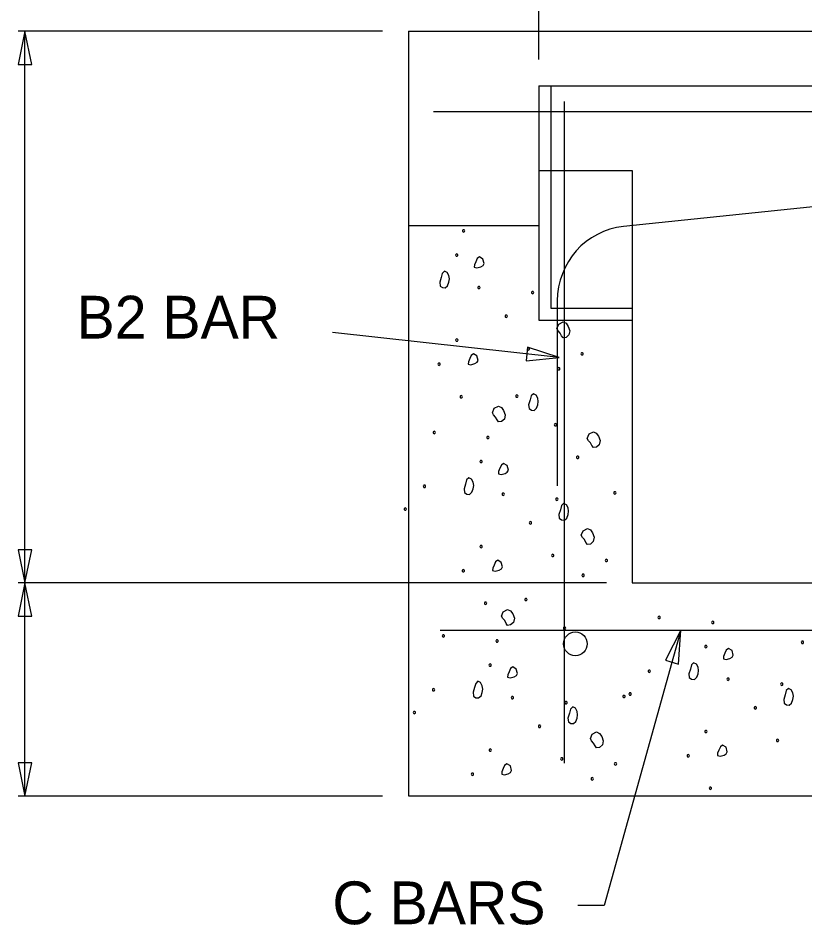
# Model space of a CAD drawing. Extents: x -439.2 to -407.9, y -458.1 to -436.2.
# Drawn here: x -415.176 to -412.38, y -445.047 to -441.825 of the extents above; entities that cross this region are included whole.
import ezdxf

# ---------------------------------------------------------------- set-up
doc = ezdxf.new("R2010")
doc.units = 0
doc.layers.add('Level 4', color=7, linetype='Continuous')

msp = doc.modelspace()

# ---------------------------------------------------------------- linework, layer by layer
at = {"layer": 'Level 4'}
for p, q in [((-413.3253, -441.9721), (-413.3253, -441.3025)), ((-413.881, -441.8718), (-415.1764, -441.8718)), ((-415.1523, -443.8317), (-415.1523, -441.8718)), ((-413.7894, -441.872), (-413.7894, -444.5887)), ((-413.7894, -441.872), (-409.204, -441.872)), ((-413.3253, -442.0658), (-409.7091, -442.0658)), ((-413.3253, -442.0658), (-413.3253, -442.8986)), ((-413.2833, -442.0658), (-413.2833, -442.856)), ((-413.236, -442.1212), (-413.236, -444.4726)), ((-413.7001, -442.1574), (-409.2933, -442.1574)), ((-413.3253, -442.3661), (-412.9935, -442.3661)), ((-411.0363, -442.3587), (-413.0244, -442.5652)), ((-412.9935, -442.3661), (-412.9935, -443.8315)), ((-413.7894, -442.5621), (-413.3253, -442.5621)), ((-413.2602, -442.8301), (-413.2602, -443.4865)), ((-413.2833, -442.856), (-412.9935, -442.856)), ((-413.3253, -442.8986), (-412.9935, -442.8986)), ((-413.2532, -443.0313), (-414.0594, -442.9419)), ((-413.0849, -443.8317), (-415.1764, -443.8317)), ((-415.1523, -444.5888), (-415.1523, -443.8317)), ((-412.9935, -443.8315), (-411.8957, -443.8315)), ((-413.676, -443.9998), (-409.2933, -443.9998)), ((-412.8209, -444), (-413.0931, -444.9774)), ((-413.881, -444.5888), (-415.1764, -444.5888)), ((-413.7894, -444.5887), (-409.204, -444.5887)), ((-413.0931, -444.9774), (-413.1873, -444.9774))]:
    msp.add_line(p, q, dxfattribs=at)
for points in [[(-415.1281, -441.9897), (-415.1523, -441.8718), (-415.1764, -441.9897)], [(-413.5372, -442.6735), (-413.545, -442.6795), (-413.5502, -442.6906), (-413.555, -442.702), (-413.5554, -442.7104), (-413.5459, -442.7127), (-413.532, -442.709), (-413.5242, -442.7042), (-413.5203, -442.6972), (-413.5246, -442.681), (-413.5372, -442.6735)], [(-413.661, -442.7243), (-413.669, -442.7319), (-413.6727, -442.7467), (-413.678, -442.7637), (-413.6766, -442.777), (-413.6684, -442.7826), (-413.6584, -442.7836), (-413.65, -442.7761), (-413.6455, -442.7638), (-413.6436, -442.7519), (-413.6455, -442.7401), (-413.6515, -442.7291), (-413.661, -442.7243)], [(-413.2615, -442.9283), (-413.2549, -442.9123), (-413.2394, -442.9046), (-413.2291, -442.9095), (-413.2212, -442.9204), (-413.2155, -442.9358), (-413.2186, -442.9506), (-413.2287, -442.9596), (-413.2394, -442.9612), (-413.2448, -442.954), (-413.2498, -442.9441), (-413.2568, -442.9364), (-413.2615, -442.9283)], [(-413.5583, -443.0173), (-413.5661, -443.0233), (-413.5713, -443.0344), (-413.576, -443.0458), (-413.5764, -443.0541), (-413.567, -443.0565), (-413.5531, -443.0528), (-413.5453, -443.048), (-413.5414, -443.041), (-413.5456, -443.0248), (-413.5583, -443.0173)], [(-413.3713, -443.0428), (-413.2532, -443.0313), (-413.366, -442.9942)], [(-413.3451, -443.1594), (-413.353, -443.1669), (-413.3567, -443.1818), (-413.362, -443.1988), (-413.3606, -443.212), (-413.3524, -443.2177), (-413.3425, -443.2186), (-413.334, -443.2111), (-413.3295, -443.1989), (-413.3277, -443.187), (-413.3295, -443.1752), (-413.3355, -443.1642), (-413.3451, -443.1594)], [(-413.491, -443.227), (-413.4845, -443.2111), (-413.469, -443.2033), (-413.4587, -443.2083), (-413.4508, -443.2191), (-413.4451, -443.2346), (-413.4482, -443.2494), (-413.4583, -443.2584), (-413.469, -443.2599), (-413.4744, -443.2528), (-413.4794, -443.2428), (-413.4864, -443.2351), (-413.491, -443.227)], [(-413.154, -443.3183), (-413.1474, -443.3024), (-413.1319, -443.2946), (-413.1216, -443.2995), (-413.1138, -443.3104), (-413.1081, -443.3259), (-413.1112, -443.3407), (-413.1212, -443.3497), (-413.1319, -443.3512), (-413.1374, -443.3441), (-413.1423, -443.3341), (-413.1493, -443.3264), (-413.154, -443.3183)], [(-413.4508, -443.4073), (-413.4586, -443.4133), (-413.4638, -443.4244), (-413.4686, -443.4358), (-413.469, -443.4442), (-413.4595, -443.4466), (-413.4456, -443.4429), (-413.4378, -443.438), (-413.4339, -443.431), (-413.4382, -443.4148), (-413.4508, -443.4073)], [(-413.5746, -443.4581), (-413.5826, -443.4657), (-413.5863, -443.4805), (-413.5916, -443.4975), (-413.5902, -443.5108), (-413.582, -443.5165), (-413.572, -443.5174), (-413.5636, -443.5099), (-413.5591, -443.4976), (-413.5572, -443.4857), (-413.5591, -443.4739), (-413.5651, -443.463), (-413.5746, -443.4581)], [(-413.2376, -443.5494), (-413.2455, -443.557), (-413.2493, -443.5718), (-413.2546, -443.5888), (-413.2532, -443.6021), (-413.245, -443.6078), (-413.235, -443.6087), (-413.2266, -443.6012), (-413.222, -443.5889), (-413.2202, -443.577), (-413.222, -443.5652), (-413.228, -443.5543), (-413.2376, -443.5494)], [(-413.1751, -443.6621), (-413.1685, -443.6461), (-413.153, -443.6384), (-413.1427, -443.6433), (-413.1348, -443.6542), (-413.1291, -443.6697), (-413.1322, -443.6845), (-413.1423, -443.6935), (-413.153, -443.695), (-413.1585, -443.6879), (-413.1634, -443.6779), (-413.1704, -443.6702), (-413.1751, -443.6621)], [(-415.1764, -443.7139), (-415.1523, -443.8317), (-415.1281, -443.7139)], [(-413.4719, -443.7511), (-413.4797, -443.7571), (-413.4849, -443.7682), (-413.4896, -443.7796), (-413.4901, -443.788), (-413.4806, -443.7904), (-413.4667, -443.7867), (-413.4589, -443.7818), (-413.455, -443.7748), (-413.4593, -443.7586), (-413.4719, -443.7511)], [(-415.1281, -443.9496), (-415.1523, -443.8317), (-415.1764, -443.9496)], [(-413.4586, -443.9499), (-413.4521, -443.9339), (-413.4366, -443.9262), (-413.4263, -443.9311), (-413.4184, -443.942), (-413.4127, -443.9575), (-413.4158, -443.9723), (-413.4259, -443.9812), (-413.4366, -443.9828), (-413.442, -443.9757), (-413.447, -443.9657), (-413.454, -443.958), (-413.4586, -443.9499)], [(-412.8292, -444.12), (-412.8209, -444), (-412.8757, -444.1067)], [(-412.6517, -444.0645), (-412.6595, -444.0705), (-412.6647, -444.0816), (-412.6695, -444.093), (-412.6699, -444.1014), (-412.6604, -444.1037), (-412.6465, -444.1), (-412.6387, -444.0952), (-412.6348, -444.0882), (-412.6391, -444.072), (-412.6517, -444.0645)], [(-412.7755, -444.1153), (-412.7835, -444.1228), (-412.7872, -444.1377), (-412.7925, -444.1547), (-412.7911, -444.168), (-412.7829, -444.1736), (-412.7729, -444.1746), (-412.7645, -444.1671), (-412.76, -444.1548), (-412.7581, -444.1429), (-412.76, -444.1311), (-412.766, -444.1201), (-412.7755, -444.1153)], [(-413.4184, -444.1302), (-413.4262, -444.1362), (-413.4314, -444.1473), (-413.4362, -444.1587), (-413.4366, -444.1671), (-413.4271, -444.1694), (-413.4132, -444.1658), (-413.4055, -444.1609), (-413.4015, -444.1539), (-413.4058, -444.1377), (-413.4184, -444.1302)], [(-413.5422, -444.181), (-413.5502, -444.1886), (-413.5539, -444.2034), (-413.5592, -444.2204), (-413.5578, -444.2337), (-413.5496, -444.2394), (-413.5397, -444.2403), (-413.5312, -444.2328), (-413.5267, -444.2205), (-413.5248, -444.2086), (-413.5267, -444.1968), (-413.5327, -444.1858), (-413.5422, -444.181)], [(-412.4385, -444.2066), (-412.4464, -444.2141), (-412.4502, -444.229), (-412.4555, -444.246), (-412.4541, -444.2593), (-412.4459, -444.2649), (-412.4359, -444.2658), (-412.4275, -444.2584), (-412.4229, -444.2461), (-412.4211, -444.2342), (-412.4229, -444.2224), (-412.4289, -444.2114), (-412.4385, -444.2066)], [(-413.2052, -444.2723), (-413.2131, -444.2799), (-413.2169, -444.2947), (-413.2222, -444.3117), (-413.2208, -444.325), (-413.2126, -444.3306), (-413.2026, -444.3316), (-413.1942, -444.3241), (-413.1896, -444.3118), (-413.1878, -444.2999), (-413.1896, -444.2881), (-413.1956, -444.2771), (-413.2052, -444.2723)], [(-413.1427, -444.385), (-413.1361, -444.369), (-413.1206, -444.3613), (-413.1103, -444.3662), (-413.1024, -444.3771), (-413.0967, -444.3926), (-413.0998, -444.4074), (-413.1099, -444.4163), (-413.1206, -444.4179), (-413.1261, -444.4107), (-413.131, -444.4008), (-413.138, -444.3931), (-413.1427, -444.385)], [(-412.6728, -444.4083), (-412.6806, -444.4143), (-412.6858, -444.4254), (-412.6905, -444.4368), (-412.6909, -444.4451), (-412.6815, -444.4475), (-412.6676, -444.4438), (-412.6598, -444.439), (-412.6559, -444.432), (-412.6601, -444.4158), (-412.6728, -444.4083)], [(-415.1764, -444.471), (-415.1523, -444.5888), (-415.1281, -444.471)], [(-413.4395, -444.474), (-413.4473, -444.48), (-413.4525, -444.4911), (-413.4572, -444.5025), (-413.4577, -444.5109), (-413.4482, -444.5132), (-413.4343, -444.5095), (-413.4265, -444.5047), (-413.4226, -444.4977), (-413.4269, -444.4815), (-413.4395, -444.474)]]:
    msp.add_lwpolyline(points, close=True, dxfattribs=at)
for centre, major_axis, start_param, end_param in [((-412.9977, -442.8301), (0, 0.2662), 0.102079, 1.570796), ((-413.593, -442.5812), (0, 0.00422), 4.712389, 7.853982), ((-413.593, -442.5812), (0, 0.00422), 1.570796, 4.712389), ((-413.6176, -442.667), (0, 0.00422), 4.712389, 7.853982), ((-413.6176, -442.667), (0, 0.00422), 1.570796, 4.712389), ((-413.5387, -442.7826), (0, 0.00422), 4.712389, 7.853982), ((-413.5387, -442.7826), (0, 0.00422), 1.570796, 4.712389), ((-413.3479, -442.8004), (0, 0.00422), 4.712389, 7.853982), ((-413.3479, -442.8004), (0, 0.00422), 1.570796, 4.712389), ((-413.4418, -442.8845), (0, 0.00422), 4.712389, 7.853982), ((-413.4418, -442.8845), (0, 0.00422), 1.570796, 4.712389), ((-413.6172, -442.9689), (0, 0.00422), 4.712389, 7.853982), ((-413.6172, -442.9689), (0, 0.00422), 1.570796, 4.712389), ((-413.3629, -443.0002), (0, 0.00422), 4.712389, 7.853982), ((-413.3629, -443.0002), (0, 0.00422), 1.570796, 4.712389), ((-413.1721, -443.018), (0, 0.00422), 4.712389, 7.853982), ((-413.1721, -443.018), (0, 0.00422), 1.570796, 4.712389), ((-413.6805, -443.0546), (0, 0.00422), 4.712389, 7.853982), ((-413.6805, -443.0546), (0, 0.00422), 1.570796, 4.712389), ((-413.2548, -443.071), (0, 0.00422), 4.712389, 7.853982), ((-413.2548, -443.071), (0, 0.00422), 1.570796, 4.712389), ((-413.6016, -443.1703), (0, 0.00422), 4.712389, 7.853982), ((-413.6016, -443.1703), (0, 0.00422), 1.570796, 4.712389), ((-413.4039, -443.1681), (0, 0.00422), 4.712389, 7.853982), ((-413.4039, -443.1681), (0, 0.00422), 1.570796, 4.712389), ((-413.2668, -443.27), (0, 0.00422), 4.712389, 7.853982), ((-413.2668, -443.27), (0, 0.00422), 1.570796, 4.712389), ((-413.6974, -443.2973), (0, 0.00422), 4.712389, 7.853982), ((-413.6974, -443.2973), (0, 0.00422), 1.570796, 4.712389), ((-413.5066, -443.3151), (0, 0.00422), 4.712389, 7.853982), ((-413.5066, -443.3151), (0, 0.00422), 1.570796, 4.712389), ((-413.5312, -443.4008), (0, 0.00422), 4.712389, 7.853982), ((-413.5312, -443.4008), (0, 0.00422), 1.570796, 4.712389), ((-413.1878, -443.3856), (0, 0.00422), 4.712389, 7.853982), ((-413.1878, -443.3856), (0, 0.00422), 1.570796, 4.712389), ((-413.7324, -443.4885), (0, 0.00422), 4.712389, 7.853982), ((-413.7324, -443.4885), (0, 0.00422), 1.570796, 4.712389), ((-413.4523, -443.5165), (0, 0.00422), 4.712389, 7.853982), ((-413.4523, -443.5165), (0, 0.00422), 1.570796, 4.712389), ((-413.2615, -443.5343), (0, 0.00422), 4.712389, 7.853982), ((-413.2615, -443.5343), (0, 0.00422), 1.570796, 4.712389), ((-413.0555, -443.512), (0, 0.00422), 4.712389, 7.853982), ((-413.0555, -443.512), (0, 0.00422), 1.570796, 4.712389), ((-413.8005, -443.5693), (0, 0.00422), 4.712389, 7.853982), ((-413.8005, -443.5693), (0, 0.00422), 1.570796, 4.712389), ((-413.3554, -443.6183), (0, 0.00422), 4.712389, 7.853982), ((-413.3554, -443.6183), (0, 0.00422), 1.570796, 4.712389), ((-413.5308, -443.7027), (0, 0.00422), 4.712389, 7.853982), ((-413.5308, -443.7027), (0, 0.00422), 1.570796, 4.712389), ((-413.2765, -443.734), (0, 0.00422), 4.712389, 7.853982), ((-413.2765, -443.734), (0, 0.00422), 1.570796, 4.712389), ((-413.0857, -443.7518), (0, 0.00422), 4.712389, 7.853982), ((-413.0857, -443.7518), (0, 0.00422), 1.570796, 4.712389), ((-413.5941, -443.7884), (0, 0.00422), 4.712389, 7.853982), ((-413.5941, -443.7884), (0, 0.00422), 1.570796, 4.712389), ((-413.1684, -443.8048), (0, 0.00422), 4.712389, 7.853982), ((-413.1684, -443.8048), (0, 0.00422), 1.570796, 4.712389), ((-413.3715, -443.891), (0, 0.00422), 4.712389, 7.853982), ((-413.3715, -443.891), (0, 0.00422), 1.570796, 4.712389), ((-413.5152, -443.9041), (0, 0.00422), 4.712389, 7.853982), ((-413.5152, -443.9041), (0, 0.00422), 1.570796, 4.712389), ((-412.8983, -443.9545), (0, 0.00422), 4.712389, 7.853982), ((-412.8983, -443.9545), (0, 0.00422), 1.570796, 4.712389), ((-413.2344, -443.9928), (0, 0.00422), 4.712389, 7.853982), ((-412.7075, -443.9722), (0, 0.00422), 4.712389, 7.853982), ((-412.7075, -443.9722), (0, 0.00422), 1.570796, 4.712389), ((-413.665, -444.0202), (0, 0.00422), 4.712389, 7.853982), ((-413.665, -444.0202), (0, 0.00422), 1.570796, 4.712389), ((-413.2344, -443.9928), (0, 0.00422), 1.570796, 4.712389), ((-413.4742, -444.038), (0, 0.00422), 4.712389, 7.853982), ((-413.4742, -444.038), (0, 0.00422), 1.570796, 4.712389), ((-412.7321, -444.058), (0, 0.00422), 4.712389, 7.853982), ((-412.3887, -444.0428), (0, 0.00422), 4.712389, 7.853982), ((-412.3887, -444.0428), (0, 0.00422), 1.570796, 4.712389), ((-412.7321, -444.058), (0, 0.00422), 1.570796, 4.712389), ((-413.4988, -444.1237), (0, 0.00422), 4.712389, 7.853982), ((-413.4988, -444.1237), (0, 0.00422), 1.570796, 4.712389), ((-412.9333, -444.1456), (0, 0.00422), 4.712389, 7.853982), ((-412.9333, -444.1456), (0, 0.00422), 1.570796, 4.712389), ((-412.6532, -444.1736), (0, 0.00422), 4.712389, 7.853982), ((-412.6532, -444.1736), (0, 0.00422), 1.570796, 4.712389), ((-413.7, -444.2113), (0, 0.00422), 4.712389, 7.853982), ((-413.7, -444.2113), (0, 0.00422), 1.570796, 4.712389), ((-412.4624, -444.1914), (0, 0.00422), 4.712389, 7.853982), ((-412.4624, -444.1914), (0, 0.00422), 1.570796, 4.712389), ((-413.4199, -444.2393), (0, 0.00422), 4.712389, 7.853982), ((-413.4199, -444.2393), (0, 0.00422), 1.570796, 4.712389), ((-413.0231, -444.2349), (0, 0.00422), 4.712389, 7.853982), ((-413.0231, -444.2349), (0, 0.00422), 1.570796, 4.712389), ((-413.0014, -444.2264), (0, 0.00422), 4.712389, 7.853982), ((-413.0014, -444.2264), (0, 0.00422), 1.570796, 4.712389), ((-413.2291, -444.2571), (0, 0.00422), 4.712389, 7.853982), ((-413.2291, -444.2571), (0, 0.00422), 1.570796, 4.712389), ((-412.5563, -444.2755), (0, 0.00422), 4.712389, 7.853982), ((-412.5563, -444.2755), (0, 0.00422), 1.570796, 4.712389), ((-413.7681, -444.2922), (0, 0.00422), 4.712389, 7.853982), ((-413.7681, -444.2922), (0, 0.00422), 1.570796, 4.712389), ((-413.3231, -444.3412), (0, 0.00422), 4.712389, 7.853982), ((-413.3231, -444.3412), (0, 0.00422), 1.570796, 4.712389), ((-412.7317, -444.3599), (0, 0.00422), 4.712389, 7.853982), ((-412.7317, -444.3599), (0, 0.00422), 1.570796, 4.712389), ((-412.4774, -444.3912), (0, 0.00422), 4.712389, 7.853982), ((-412.4774, -444.3912), (0, 0.00422), 1.570796, 4.712389), ((-413.4984, -444.4256), (0, 0.00422), 4.712389, 7.853982), ((-413.4984, -444.4256), (0, 0.00422), 1.570796, 4.712389), ((-413.2441, -444.4569), (0, 0.00422), 4.712389, 7.853982), ((-413.2441, -444.4569), (0, 0.00422), 1.570796, 4.712389), ((-413.0533, -444.4747), (0, 0.00422), 4.712389, 7.853982), ((-412.795, -444.4456), (0, 0.00422), 4.712389, 7.853982), ((-412.795, -444.4456), (0, 0.00422), 1.570796, 4.712389), ((-413.0533, -444.4747), (0, 0.00422), 1.570796, 4.712389), ((-413.5617, -444.5113), (0, 0.00422), 4.712389, 7.853982), ((-413.5617, -444.5113), (0, 0.00422), 1.570796, 4.712389), ((-413.136, -444.5277), (0, 0.00422), 4.712389, 7.853982), ((-413.136, -444.5277), (0, 0.00422), 1.570796, 4.712389), ((-412.7161, -444.5613), (0, 0.00422), 4.712389, 7.853982), ((-412.7161, -444.5613), (0, 0.00422), 1.570796, 4.712389)]:
    msp.add_ellipse(centre, major_axis=major_axis, ratio=0.985935, start_param=start_param, end_param=end_param, dxfattribs=at)
msp.add_ellipse((-413.1959, -444.0482), major_axis=(0, 0.0426), ratio=0.985935, dxfattribs=at)

# ---------------------------------------------------------------- texts
for s, p in [('B2 BAR', (-414.9689, -442.9638)), ('C BARS', (-414.0595, -445.0444))]:
    msp.add_text(s, height=0.15214, dxfattribs=at).set_placement(p)

doc.saveas('drawing.dxf')
